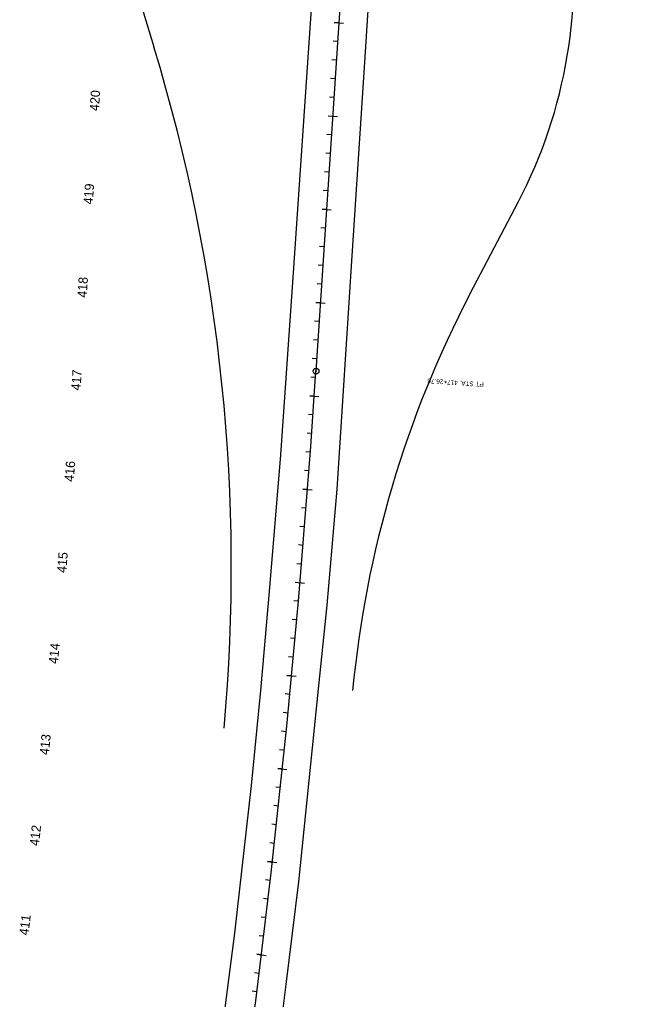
# Model space of a CAD drawing. Extents: x 1699999 to 1705087, y 475568 to 482652.
# Drawn here: x 1702748 to 1703415, y 476645 to 477692 of the extents above; entities that cross this region are included whole.
import ezdxf

# ---------------------------------------------------------------- set-up
doc = ezdxf.new("R2010")
doc.units = 0
for name, color, linetype in [('Default', 7, 'Continuous'), ('DES - DTM - Boundary', 7, 'Continuous'), ('DES - DTM - Ground', 7, 'Continuous'), ('DES - DTM - Points - High', 7, 'Continuous'), ('DESIGN - TYPICAL - Guardrail', 7, 'Continuous')]:
    doc.layers.add(name, color=color, linetype=linetype)

msp = doc.modelspace()

# ---------------------------------------------------------------- linework, layer by layer
at = {"layer": 'Default'}
for p, q in [((1703065.1, 477316.2), (1703415.3, 482625.1)), ((1703230.1, 477399.2), (1703281.3, 477496.9)), ((1703230.1, 477399.2), (1703281.3, 477496.9))]:
    msp.add_line(p, q, dxfattribs=at)
for centre, radius, start, end in [((1702819.9, 477738.6), 520.9, 332.348, 8.7908), ((1701064.6, 477106.6), 1909.9, 354.8343, 16.9351), ((1691630.7, 478070.5), 11459.2, 347.60785, 356.22594)]:
    msp.add_arc(centre, radius, start, end, dxfattribs=at)
at = {"layer": 'DES - DTM - Ground'}
for p, q in [((1703065.1, 477316.2), (1703415.3, 482625.1)), ((1702812.7, 477922.2), (1702891.6, 477662.9)), ((1703230.1, 477399.2), (1703281.3, 477496.9))]:
    msp.add_line(p, q, dxfattribs=at)
for points in [[(1702792.5, 475614.8), (1702811.9, 475706.1), (1702823.5, 475760.9), (1702852.3, 475908.3), (1702864.3, 475969.8), (1702898.6, 476166.8), (1702930.7, 476366.1), (1702944.7, 476465.1), (1702959.1, 476566.7), (1702978.3, 476715.2), (1702996.2, 476873.4), (1703005.9, 476974.9), (1703015.7, 477085.1), (1703027.3, 477226.9), (1703041.4, 477426.6), (1703058.8, 477682.8), (1703068.5, 477820.5), (1703076.7, 477939.3), (1703102.2, 478346.2), (1703125.6, 478707.3), (1703153.6, 479126.1), (1703182.2, 479545.9), (1703224.8, 480202.3)], [(1702852.1, 475601.7), (1702865.1, 475660.8), (1702881.2, 475737.3), (1702911.2, 475888.1), (1702948.6, 476084.6), (1702981.7, 476289.6), (1703003.2, 476438), (1703018.5, 476543.6), (1703033, 476660.6), (1703046.6, 476770.4), (1703067, 476969.4), (1703076.9, 477065.9), (1703087.8, 477190), (1703103.7, 477439.5), (1703117.2, 477646.5), (1703128.4, 477818.7)]]:
    msp.add_lwpolyline(points, dxfattribs=at)
for centre, radius, start, end in [((1702819.9, 477738.6), 520.9, 332.348, 8.7908), ((1701064.6, 477106.6), 1909.9, 354.8343, 16.9351), ((1704245.1, 476867.3), 1145.9, 152.348, 174.6243), ((1691630.7, 478070.5), 11459.2, 347.60785, 356.22594)]:
    msp.add_arc(centre, radius, start, end, dxfattribs=at)
at = {"layer": 'DES - DTM - Points - High'}
for p, q in [((1703084.6, 477689), (1703094.6, 477688.3)), ((1703088.3, 477668.7), (1703083.3, 477669)), ((1703087, 477648.7), (1703082, 477649.1)), ((1703085.7, 477628.8), (1703080.7, 477629.1)), ((1703084.4, 477608.8), (1703079.4, 477609.1)), ((1703078, 477589.2), (1703088, 477588.5)), ((1703081.7, 477568.9), (1703076.8, 477569.2)), ((1703080.4, 477548.9), (1703075.4, 477549.3)), ((1703079.1, 477529), (1703074.1, 477529.3)), ((1703077.8, 477509), (1703072.8, 477509.4)), ((1703071.5, 477489.4), (1703081.4, 477488.7)), ((1703075.1, 477469.1), (1703070.2, 477469.4)), ((1703073.8, 477449.2), (1703068.9, 477449.5)), ((1703072.5, 477429.2), (1703067.5, 477429.5)), ((1703071.2, 477409.2), (1703066.2, 477409.6)), ((1703064.9, 477389.6), (1703074.9, 477389)), ((1703068.6, 477369.3), (1703063.6, 477369.7)), ((1703067.2, 477349.4), (1703062.3, 477349.7)), ((1703065.9, 477329.4), (1703061, 477329.7)), ((1703064.6, 477309.5), (1703059.6, 477309.8)), ((1703058.3, 477289.8), (1703068.2, 477289.2)), ((1703061.9, 477269.6), (1703056.9, 477269.9)), ((1703060.5, 477249.6), (1703055.5, 477250)), ((1703059, 477229.7), (1703054, 477230)), ((1703057.5, 477209.7), (1703052.6, 477210.1)), ((1703051, 477190.2), (1703061, 477189.4)), ((1703054.5, 477169.8), (1703049.5, 477170.2)), ((1703052.9, 477149.9), (1703047.9, 477150.3)), ((1703051.2, 477130), (1703046.3, 477130.4)), ((1703049.6, 477110), (1703044.6, 477110.4)), ((1703042.9, 477090.5), (1703052.9, 477089.7)), ((1703046.2, 477070.2), (1703041.2, 477070.6)), ((1703044.4, 477050.3), (1703039.4, 477050.7)), ((1703042.6, 477030.3), (1703037.6, 477030.8)), ((1703040.8, 477010.4), (1703035.8, 477010.9)), ((1703033.9, 476991), (1703043.9, 476990)), ((1703037, 476970.6), (1703032, 476971.1)), ((1703035.1, 476950.7), (1703030.1, 476951.2)), ((1703033.1, 476930.8), (1703028.1, 476931.3)), ((1703031.1, 476910.9), (1703026.1, 476911.4)), ((1703024.1, 476891.5), (1703034, 476890.5)), ((1703027, 476871.1), (1703022, 476871.6)), ((1703024.9, 476851.2), (1703019.9, 476851.7)), ((1703022.7, 476831.3), (1703017.8, 476831.9)), ((1703020.5, 476811.4), (1703015.6, 476812)), ((1703013.3, 476792.1), (1703023.3, 476791)), ((1703016.1, 476771.7), (1703011.1, 476772.3)), ((1703013.8, 476751.8), (1703008.8, 476752.4)), ((1703011.5, 476732), (1703006.5, 476732.5)), ((1703009.1, 476712.1), (1703004.2, 476712.7)), ((1703001.8, 476692.8), (1703011.7, 476691.6)), ((1703004.3, 476672.4), (1702999.4, 476673)), ((1703001.8, 476652.5), (1702996.9, 476653.2))]:
    msp.add_line(p, q, dxfattribs=at)
at = {"layer": 'DESIGN - TYPICAL - Guardrail'}
for p, q in [((1703089.6, 477688.6), (1703084.7, 477689)), ((1703078, 477589.2), (1703088, 477588.5)), ((1703076.5, 477489.1), (1703071.5, 477489.4)), ((1703069.9, 477389.3), (1703064.9, 477389.6)), ((1703063.3, 477289.5), (1703058.3, 477289.8)), ((1703056, 477189.8), (1703051, 477190.2)), ((1703042.9, 477090.5), (1703052.9, 477089.7)), ((1703038.9, 476990.5), (1703033.9, 476991)), ((1703029, 476891), (1703024.1, 476891.5)), ((1703018.3, 476791.6), (1703013.4, 476792.1)), ((1703006.7, 476692.2), (1703001.8, 476692.8))]:
    msp.add_line(p, q, dxfattribs=at)
for radius in [3.14, 0.33]:
    msp.add_circle((1703065.1, 477316.2), radius, dxfattribs=at)

# ---------------------------------------------------------------- texts
at = {"layer": 'DES - DTM - Boundary'}
for s, p in [('417+26.76', (1703217, 477306.2)), (' STA. ', (1703235.8, 477304.9)), ('PT', (1703244.7, 477304.4))]:
    msp.add_text(s, height=4.98, rotation=176.2259, dxfattribs=at).set_placement(p)
at = {"layer": 'DES - DTM - Points - High'}
for s, rotation, p in [('420', 86.2259, (1702832.8, 477594.1)), ('419', 86.2259, (1702826.3, 477494.3)), ('418', 86.2259, (1702819.7, 477394.5)), ('417', 86.0922, (1702813.1, 477295.3)), ('416', 85.5922, (1702805.9, 477197.7)), ('415', 85.0922, (1702797.8, 477100.2)), ('414', 84.5922, (1702788.9, 477002.9)), ('413', 84.0922, (1702779.2, 476905.5)), ('412', 83.5922, (1702768.6, 476808.3)), ('411', 83.0922, (1702757.4, 476712.6))]:
    msp.add_text(s, height=9.96, rotation=rotation, dxfattribs=at).set_placement(p)
at = {"layer": 'DESIGN - TYPICAL - Guardrail'}
for s, rotation, p in [('420', 86.2259, (1702832.8, 477594.1)), ('415', 85.0922, (1702797.8, 477100.2))]:
    msp.add_text(s, height=9.96, rotation=rotation, dxfattribs=at).set_placement(p)

doc.saveas('drawing.dxf')
